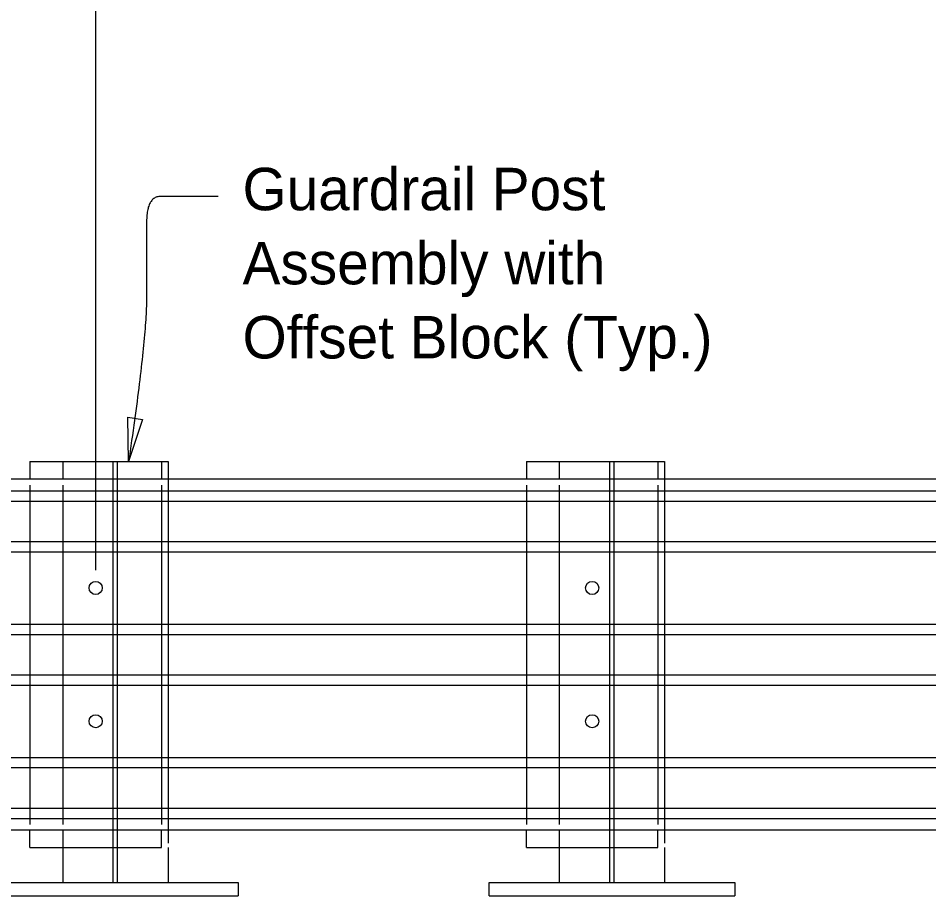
# Model space of a CAD drawing. Extents: x 21587 to 21659.1, y 56113.9 to 56155.9.
# Drawn here: x 21594.998 to 21599.323, y 56134.801 to 56138.97 of the extents above; entities that cross this region are included whole.
import ezdxf

# ---------------------------------------------------------------- set-up
doc = ezdxf.new("R2010")
doc.units = 0
for name, color, linetype in [('Border', 7, 'Continuous'), ('Patterning', 7, 'Continuous'), ('PlotBorder_dp', 7, 'Continuous'), ('TextMisc', 7, 'Continuous')]:
    doc.layers.add(name, color=color, linetype=linetype)

msp = doc.modelspace()

# ---------------------------------------------------------------- linework, layer by layer
at = {"layer": 'Border'}
for p, q in [((21595.2096, 56136.8635), (21595.7096, 56136.8635)), ((21595.2096, 56136.8635), (21595.2096, 56136.7802)), ((21597.5677, 56136.8635), (21598.0677, 56136.8635)), ((21597.5677, 56136.8635), (21597.5677, 56136.7802)), ((21599.7592, 56136.7801), (21587.6633, 56136.7801)), ((21587.6633, 56136.7246), (21599.7592, 56136.7246)), ((21587.6633, 56136.6764), (21599.7592, 56136.6764)), ((21587.6633, 56136.4835), (21599.7592, 56136.4835)), ((21587.6633, 56136.4353), (21599.7592, 56136.4353)), ((21587.6633, 56136.0914), (21599.7592, 56136.0914)), ((21587.6633, 56136.0431), (21599.7592, 56136.0431)), ((21587.6633, 56135.8503), (21599.7592, 56135.8503)), ((21587.6633, 56135.8022), (21599.7592, 56135.8022)), ((21587.6633, 56135.4582), (21599.7592, 56135.4582)), ((21587.6633, 56135.41), (21599.7592, 56135.41)), ((21587.6633, 56135.2172), (21599.7592, 56135.2172)), ((21587.6633, 56135.169), (21599.7592, 56135.169)), ((21599.7592, 56135.1134), (21587.6633, 56135.1134)), ((21595.2096, 56135.1135), (21595.2096, 56134.8635)), ((21597.5677, 56135.1135), (21597.5677, 56134.8635)), ((21595.7096, 56135.0302), (21595.7096, 56134.8635)), ((21598.0677, 56135.0302), (21598.0677, 56134.8635)), ((21594.8762, 56134.8635), (21596.0429, 56134.8635)), ((21595.2096, 56134.8635), (21595.7096, 56134.8635)), ((21596.0429, 56134.8635), (21596.0429, 56134.801)), ((21597.2344, 56134.8635), (21598.401, 56134.8635)), ((21597.2344, 56134.801), (21597.2344, 56134.8635)), ((21597.5677, 56134.8635), (21598.0677, 56134.8635)), ((21598.401, 56134.8635), (21598.401, 56134.801)), ((21594.8762, 56134.801), (21596.0429, 56134.801)), ((21597.2344, 56134.801), (21598.401, 56134.801))]:
    msp.add_line(p, q, dxfattribs=at)
for centre in [(21595.3658, 56136.2634), (21597.724, 56136.2634), (21595.3658, 56135.6303), (21597.724, 56135.6303)]:
    msp.add_circle(centre, 0.0312, dxfattribs=at)
at = {"layer": 'Patterning'}
for p, q in [((21595.4491, 56134.8635), (21595.4491, 56136.8635)), ((21595.47, 56134.8635), (21595.47, 56136.8635)), ((21595.7096, 56136.8635), (21595.7096, 56135.0505)), ((21597.8073, 56134.8635), (21597.8073, 56136.8635)), ((21597.8281, 56134.8635), (21597.8281, 56136.8635)), ((21598.0677, 56136.8635), (21598.0677, 56135.0505)), ((21595.2096, 56136.7516), (21595.2096, 56135.1398)), ((21597.5677, 56136.7516), (21597.5677, 56135.1398))]:
    msp.add_line(p, q, dxfattribs=at)
at = {"layer": 'PlotBorder_dp'}
msp.add_line((21595.3658, 56136.3484), (21595.3658, 56141.1869), dxfattribs=at)
msp.add_lwpolyline([(21595.5221, 56136.8635), (21595.5179, 56137.0747), (21595.5877, 56137.0643)], close=True, dxfattribs=at)
msp.add_open_spline([(21595.947, 56138.1237), (21595.7421, 56138.1237), (21595.6078, 56138.1237), (21595.6078, 56137.8833), (21595.6078, 56137.4378), (21595.5221, 56136.8635)], degree=2, dxfattribs=at)
at = {"layer": 'TextMisc'}
for p, q in [((21595.0533, 56136.8635), (21595.6783, 56136.8635)), ((21595.0533, 56136.8635), (21595.0533, 56136.7802)), ((21595.6783, 56136.8635), (21595.6783, 56136.7802)), ((21597.4115, 56136.8635), (21598.0365, 56136.8635)), ((21597.4115, 56136.8635), (21597.4115, 56136.7802)), ((21598.0365, 56136.8635), (21598.0365, 56136.7802)), ((21595.0533, 56136.7516), (21595.0533, 56135.1398)), ((21595.6783, 56136.7516), (21595.6783, 56135.1398)), ((21597.4115, 56136.7516), (21597.4115, 56135.1398)), ((21598.0365, 56136.7516), (21598.0365, 56135.1398)), ((21595.0533, 56135.0302), (21595.0533, 56135.1135)), ((21595.6783, 56135.0302), (21595.6783, 56135.1135)), ((21597.4115, 56135.0302), (21597.4115, 56135.1135)), ((21598.0365, 56135.0302), (21598.0365, 56135.1135)), ((21595.0533, 56135.0302), (21595.6783, 56135.0302)), ((21597.4115, 56135.0302), (21598.0365, 56135.0302))]:
    msp.add_line(p, q, dxfattribs=at)

# ---------------------------------------------------------------- texts
at = {"layer": 'PlotBorder_dp'}
for s, p in [('Guardrail Post ', (21596.0633, 56138.0579)), ('Assembly with ', (21596.0633, 56137.7059)), ('Offset Block (Typ.)', (21596.0633, 56137.3539))]:
    msp.add_text(s, height=0.2016, dxfattribs=at).set_placement(p)

doc.saveas('drawing.dxf')
